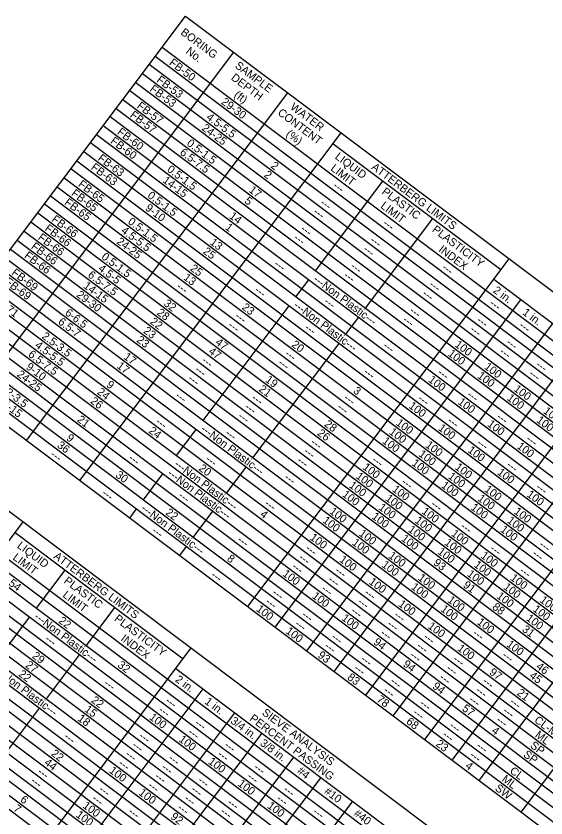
# Model space of a CAD drawing. Extents: x 627484.2 to 627514.4, y 367972.1 to 367996.9.
# Drawn here: x 627508.72 to 627512.36, y 367980.14 to 367985.65 of the extents above; entities that cross this region are included whole.
import ezdxf

# ---------------------------------------------------------------- set-up
doc = ezdxf.new("R2010")
doc.units = 0
doc.layers.add('Default', color=7, linetype='Continuous')
doc.layers.add('R_Survey Control', color=7, linetype='Continuous')

msp = doc.modelspace()

# ---------------------------------------------------------------- linework, layer by layer
at = {"layer": 'Default'}
for p, q in [((627508.0877, 367983.2583), (627509.8821, 367985.648)), ((627509.8821, 367985.648), (627514.3574, 367982.2875)), ((627508.4191, 367983.0095), (627510.2135, 367985.3992)), ((627509.7211, 367985.4336), (627514.1964, 367982.0731)), ((627509.6743, 367985.3712), (627514.1495, 367982.0107)), ((627509.6333, 367985.3166), (627514.1086, 367981.9561)), ((627509.5865, 367985.2543), (627514.0617, 367981.8938)), ((627509.5396, 367985.1919), (627514.0149, 367981.8314)), ((627509.4987, 367985.1373), (627513.9739, 367981.7768)), ((627508.7894, 367982.7314), (627510.5838, 367985.1211)), ((627509.4518, 367985.075), (627513.9271, 367981.7145)), ((627509.405, 367985.0126), (627513.8802, 367981.6521)), ((627509.364, 367984.958), (627513.8393, 367981.5975)), ((627509.1559, 367982.4563), (627510.9503, 367984.8459)), ((627509.3172, 367984.8956), (627513.7924, 367981.5351)), ((627509.2703, 367984.8333), (627513.7456, 367981.4728)), ((627509.2294, 367984.7787), (627513.7046, 367981.4182)), ((627510.8947, 367984.7719), (627512.0486, 367983.9054)), ((627509.1825, 367984.7163), (627513.6578, 367981.3558)), ((627509.1357, 367984.6539), (627513.6109, 367981.2934)), ((627509.0947, 367984.5994), (627513.57, 367981.2389)), ((627509.0479, 367984.537), (627513.5231, 367981.1765)), ((627509.001, 367984.4746), (627513.4763, 367981.1141)), ((627510.7752, 367983.8983), (627511.2377, 367984.5143)), ((627508.9542, 367984.4122), (627513.4294, 367981.0517)), ((627508.9132, 367984.3577), (627513.3885, 367980.9972)), ((627508.8664, 367984.2953), (627513.3416, 367980.9348)), ((627511.1182, 367983.6407), (627511.5808, 367984.2567)), ((627508.8195, 367984.2329), (627513.2948, 367980.8724)), ((627508.7727, 367984.1705), (627513.248, 367980.81)), ((627508.7259, 367984.1082), (627513.2011, 367980.7477)), ((627508.679, 367984.0458), (627513.1543, 367980.6853)), ((627508.638, 367983.9912), (627513.1133, 367980.6307)), ((627510.3098, 367981.5898), (627512.1042, 367983.9795)), ((627508.5912, 367983.9289), (627513.0665, 367980.5684)), ((627508.5444, 367983.8665), (627513.0196, 367980.506)), ((627508.5034, 367983.8119), (627512.9786, 367980.4514)), ((627510.6405, 367983.719), (627510.7284, 367983.836)), ((627511.9988, 367983.8391), (627513.5893, 367982.6448)), ((627508.4566, 367983.7495), (627512.9318, 367980.389)), ((627510.4969, 367981.4493), (627512.1859, 367983.6986)), ((627508.4097, 367983.6872), (627512.885, 367980.3267)), ((627510.0024, 367982.8692), (627510.5937, 367983.6566)), ((627508.3629, 367983.6248), (627512.8381, 367980.2643)), ((627510.9836, 367983.4614), (627511.0714, 367983.5784)), ((627508.3161, 367983.5624), (627512.7913, 367980.2019)), ((627510.7152, 367981.2854), (627512.4042, 367983.5347)), ((627508.2692, 367983.5), (627512.7445, 367980.1395)), ((627508.2282, 367983.4455), (627512.7035, 367980.085)), ((627508.1814, 367983.3831), (627512.6566, 367980.0226)), ((627510.3454, 367982.6116), (627510.9368, 367983.399)), ((627510.9023, 367981.1449), (627512.5913, 367983.3942)), ((627508.1346, 367983.3207), (627512.6098, 367979.9602)), ((627508.0877, 367983.2583), (627512.563, 367979.8978)), ((627511.1206, 367980.9809), (627512.8096, 367983.2303)), ((627511.3077, 367980.8404), (627512.9968, 367983.0897)), ((627507.6986, 367982.9746), (627512.1738, 367979.6141)), ((627511.526, 367980.6765), (627513.2151, 367982.9258)), ((627507.5376, 367982.7602), (627512.0128, 367979.3997)), ((627509.8209, 367982.6275), (627509.9556, 367982.8068)), ((627511.7131, 367980.536), (627513.4022, 367982.7853)), ((627511.9003, 367980.3955), (627513.6947, 367982.7851)), ((627507.4937, 367982.7017), (627511.9689, 367979.3412)), ((627507.4468, 367982.6393), (627511.9221, 367979.2788)), ((627507.4, 367982.5769), (627511.8753, 367979.2164)), ((627510.164, 367982.3699), (627510.2986, 367982.5492)), ((627512.1887, 367980.1789), (627513.9831, 367982.5685)), ((627507.3532, 367982.5146), (627511.8284, 367979.1541)), ((627509.5926, 367982.3234), (627509.7272, 367982.5027)), ((627507.3122, 367982.46), (627511.7874, 367979.0995)), ((627507.2654, 367982.3976), (627511.7406, 367979.0371)), ((627507.2185, 367982.3352), (627511.6938, 367978.9747)), ((627507.1717, 367982.2729), (627511.6469, 367978.9124)), ((627509.4989, 367982.1987), (627509.5457, 367982.261)), ((627507.1248, 367982.2105), (627511.6001, 367978.85)), ((627509.9356, 367982.0658), (627510.0703, 367982.2451)), ((627506.9577, 367979.7633), (627508.7667, 367982.1725)), ((627507.078, 367982.1481), (627511.5533, 367978.7876)), ((627507.037, 367982.0936), (627511.5123, 367978.733)), ((627508.7111, 367982.0984), (627509.865, 367981.232)), ((627506.9902, 367982.0312), (627511.4654, 367978.6707)), ((627509.842, 367981.9411), (627509.8888, 367982.0034)), ((627506.9434, 367981.9688), (627511.4186, 367978.6083)), ((627506.8965, 367981.9064), (627511.3718, 367978.5459)), ((627506.8497, 367981.8441), (627511.3249, 367978.4836)), ((627508.858, 367981.5796), (627509.0542, 367981.8408)), ((627506.8087, 367981.7895), (627511.2839, 367978.429)), ((627506.7619, 367981.7271), (627511.2371, 367978.3666)), ((627506.715, 367981.6647), (627511.1903, 367978.3042)), ((627509.2011, 367981.322), (627509.3972, 367981.5832)), ((627508.5829, 367981.2132), (627508.8112, 367981.5173)), ((627508.1116, 367978.8969), (627509.9206, 367981.306)), ((627508.9259, 367980.9556), (627509.1542, 367981.2597)), ((627509.8152, 367981.1657), (627511.4057, 367979.9714)), ((627508.2987, 367978.7564), (627510.0024, 367981.0252)), ((627508.0126, 367979.7393), (627508.8791, 367980.8932)), ((627508.517, 367978.5924), (627510.2207, 367980.8613)), ((627508.7041, 367978.4519), (627510.4078, 367980.7207)), ((627508.9224, 367978.288), (627510.6261, 367980.5568)), ((627509.1095, 367978.1475), (627510.8132, 367980.4163)), ((627509.3278, 367977.9836), (627511.0315, 367980.2524))]:
    msp.add_line(p, q, dxfattribs=at)
at = {"layer": 'R_Survey Control'}
msp.add_line((627509.8821, 367985.648), (627509.8821, 367985.648), dxfattribs=at)

# ---------------------------------------------------------------- texts
at = {"layer": 'Default'}
for s, p in [('BORING', (627509.844, 367985.5262)), ('No.', (627509.8796, 367985.3963)), ('FB-50', (627509.765, 367985.3175)), ('SAMPLE', (627510.2171, 367985.2976)), ('FB-53', (627509.6787, 367985.1994)), ('DEPTH', (627510.1902, 367985.2146)), ('FB-53', (627509.6319, 367985.137)), ('(ft)', (627510.21, 367985.0966)), ('29-30', (627510.1231, 367985.0486)), ('FB-57', (627509.5428, 367985.021)), ('WATER', (627510.5964, 367985.0128)), ('FB-57', (627509.496, 367984.9586)), ('4.5-5.5', (627510.02, 367984.9431)), ('CONTENT', (627510.5104, 367984.9742)), ('24-25', (627509.9894, 367984.8686)), ('FB-60', (627509.4079, 367984.8419)), ('(%)', (627510.5676, 367984.8281)), ('FB-60', (627509.3611, 367984.7795)), ('0.5-1.5', (627509.8854, 367984.7638)), ('6.5-7.5', (627509.8385, 367984.7014)), ('FB-63', (627509.2748, 367984.6614)), ('LIQUID', (627510.9038, 367984.6724)), ('FB-63', (627509.2279, 367984.599)), ('2', (627510.4634, 367984.6102)), ('LIMIT', (627510.874, 367984.5917)), ('ATTERBERG LIMITS', (627511.1544, 367984.6004)), ('0.5-1.5', (627509.7507, 367984.5845)), ('2', (627510.4166, 367984.5478)), ('FB-65', (627509.1396, 367984.4825)), ('14-15', (627509.7201, 367984.5099)), ('FB-65', (627509.0927, 367984.4201)), ('17', (627510.3126, 367984.443)), ('---', (627510.8897, 367984.473)), ('PLASTIC', (627511.2256, 367984.4308)), ('0.5-1.5', (627509.6161, 367984.4051)), ('5', (627510.2827, 367984.3679)), ('FB-65', (627509.0459, 367984.3578)), ('9-10', (627509.6007, 367984.3191)), ('---', (627510.8019, 367984.356)), ('LIMIT', (627511.217, 367984.3341)), ('14', (627510.1776, 367984.2639)), ('---', (627510.755, 367984.2936)), ('FB-66', (627508.9572, 367984.2415)), ('0.5-1.5', (627509.4814, 367984.2258)), ('FB-66', (627508.9103, 367984.1791)), ('4.5-5.5', (627509.4346, 367984.1635)), ('1', (627510.1499, 367984.1872)), ('---', (627510.6672, 367984.1767)), ('---', (627511.2327, 367984.2154)), ('PLASTICITY', (627511.5718, 367984.1709)), ('FB-66', (627508.8635, 367984.1167)), ('---', (627510.6204, 367984.1143)), ('FB-66', (627508.8167, 367984.0544)), ('24-25', (627509.404, 367984.0889)), ('13', (627510.0446, 367984.0834)), ('---', (627511.1449, 367984.0984)), ('INDEX', (627511.6161, 367984.0344)), ('FB-66', (627508.7698, 367983.992)), ('0.5-1.5', (627509.2999, 367983.9841)), ('25', (627509.9972, 367984.0214)), ('---', (627511.0981, 367984.036)), ('FB-69', (627508.6822, 367983.8749)), ('4.5-5', (627509.2774, 367983.9035)), ('25', (627509.9093, 367983.9045)), ('---', (627510.4857, 367983.935)), ('---', (627511.0103, 367983.9191)), ('---', (627511.6382, 367983.9109)), ('6.5-7.5', (627509.2062, 367983.8594)), ('13', (627509.8631, 367983.8417)), ('---', (627510.9634, 367983.8567)), ('FB-69', (627508.6353, 367983.8126)), ('14-15', (627509.1756, 367983.7848)), ('---Non Plastic---', (627510.7548, 367983.8305)), ('---', (627511.5503, 367983.794)), ('29-30', (627509.1278, 367983.7232)), ('---', (627509.8148, 367983.7804)), ('---', (627510.3511, 367983.7557)), ('---', (627511.5035, 367983.7316)), ('2 in.', (627511.9898, 367983.7536)), ('FB-71', (627508.5501, 367983.6937)), ('32', (627509.7271, 367983.6634)), ('---', (627510.8288, 367983.6774)), ('6-6.5', (627509.0491, 367983.5994)), ('28', (627509.6807, 367983.6006)), ('23', (627510.2646, 367983.6377)), ('---Non Plastic---', (627510.6202, 367983.6511)), ('---', (627511.9656, 367983.665)), ('1 in.', (627512.1925, 367983.6014)), ('---', (627510.2164, 367983.5764)), ('---', (627511.4157, 367983.6147)), ('6.5-7', (627509.0016, 367983.5375)), ('22', (627509.6334, 367983.5386)), ('---', (627510.1696, 367983.514)), ('---', (627511.3689, 367983.5523)), ('---', (627511.8778, 367983.5481)), ('---', (627512.1683, 367983.5128)), ('2.5-3.5', (627508.8901, 367983.4384)), ('23', (627509.5879, 367983.4753)), ('---', (627510.6941, 367983.4981)), ('---', (627511.831, 367983.4857)), ('23', (627509.5411, 367983.4129)), ('47', (627510.0819, 367983.3969)), ('20', (627510.6061, 367983.3812)), ('100', (627511.7267, 367983.3811)), ('---', (627512.0805, 367983.3959)), ('4.5-5.5', (627508.8433, 367983.376)), ('47', (627510.0351, 367983.3346)), ('---', (627511.2342, 367983.373)), ('6.5-7.5', (627508.7964, 367983.3136)), ('17', (627509.452, 367983.2969)), ('---', (627510.5595, 367983.3188)), ('100', (627511.6799, 367983.3187)), ('---', (627512.0337, 367983.3335)), ('9-10', (627508.7811, 367983.2276)), ('17', (627509.4052, 367983.2345)), ('---', (627509.9881, 367983.2723)), ('---', (627510.5126, 367983.2564)), ('100', (627511.9295, 367983.2289)), ('---', (627512.2832, 367983.2437)), ('24-25', (627508.719, 367983.1767)), ('---', (627509.9413, 367983.2099)), ('---', (627511.0995, 367983.1936)), ('---', (627511.6085, 367983.1894)), ('100', (627511.8826, 367983.1665)), ('---', (627512.2364, 367983.1813)), ('9', (627509.3335, 367983.1054)), ('---', (627509.8944, 367983.1475)), ('19', (627510.4249, 367983.1394)), ('100', (627511.5453, 367983.1394)), ('2-3.5', (627508.6393, 367983.0536)), ('24', (627509.2702, 367983.0554)), ('21', (627510.3806, 367983.0751)), ('3', (627511.0294, 367983.0634)), ('100', (627512.1322, 367983.0766)), ('14-15', (627508.5843, 367982.9974)), ('26', (627509.2235, 367982.993)), ('---', (627509.8066, 367983.0306)), ('---', (627510.3311, 367983.0147)), ('---', (627510.9649, 367983.0143)), ('---', (627511.4738, 367983.0101)), ('---', (627511.8112, 367983.0372)), ('100', (627512.0853, 367983.0143)), ('100', (627511.4106, 367982.9601)), ('100', (627511.748, 367982.9872)), ('---', (627510.2843, 367982.9523)), ('---', (627510.9181, 367982.9519)), ('100', (627512.3349, 367982.9244)), ('21', (627509.1325, 367982.8662)), ('---', (627509.6719, 367982.8513)), ('---', (627510.2375, 367982.8899)), ('28', (627510.8308, 367982.8346)), ('100', (627511.3228, 367982.8431)), ('---', (627511.6766, 367982.8579)), ('100', (627511.9507, 367982.835)), ('---', (627512.0139, 367982.885)), ('100', (627512.288, 367982.8621)), ('24', (627509.6249, 367982.789)), ('---Non Plastic---', (627509.982, 367982.8013)), ('26', (627510.7833, 367982.7727)), ('100', (627511.2759, 367982.7807)), ('100', (627511.6133, 367982.8078)), ('9', (627509.0584, 367982.739)), ('---', (627510.1497, 367982.773)), ('36', (627508.9951, 367982.6889)), ('---', (627510.7366, 367982.7102)), ('100', (627511.2291, 367982.7184)), ('100', (627511.5255, 367982.6909)), ('---', (627511.8793, 367982.7057)), ('100', (627512.1534, 367982.6827)), ('---', (627512.2166, 367982.7328)), ('---', (627508.9484, 367982.6265)), ('---', (627510.6897, 367982.6479)), ('100', (627511.4787, 367982.6285)), ('100', (627511.816, 367982.6556)), ('---', (627509.4846, 367982.6018)), ('---', (627510.015, 367982.5937)), ('---', (627510.6429, 367982.5855)), ('---', (627511.1577, 367982.5891)), ('100', (627511.4318, 367982.5662)), ('---Non Plastic---', (627509.8006, 367982.5596)), ('20', (627509.968, 367982.5314)), ('100', (627511.0945, 367982.5391)), ('100', (627511.7282, 367982.5387)), ('100', (627512.0187, 367982.5034)), ('---', (627512.082, 367982.5535)), ('30', (627509.3966, 367982.4849)), ('---Non Plastic---', (627509.7537, 367982.4972)), ('---', (627510.5551, 367982.4686)), ('100', (627511.0476, 367982.4767)), ('100', (627511.6814, 367982.4763)), ('100', (627511.0008, 367982.4143)), ('---', (627511.3604, 367982.4369)), ('100', (627511.6345, 367982.4139)), ('---', (627509.3031, 367982.3601)), ('100', (627510.9539, 367982.3519)), ('100', (627511.2972, 367982.3868)), ('100', (627511.9309, 367982.3865)), ('100', (627512.2214, 367982.3512)), ('---', (627512.2847, 367982.4012)), ('---', (627509.8277, 367982.3442)), ('100', (627511.2503, 367982.3245)), ('100', (627511.8841, 367982.3241)), ('---Non Plastic---', (627509.5722, 367982.2555)), ('22', (627509.7399, 367982.2272)), ('---', (627510.4204, 367982.2892)), ('100', (627510.8661, 367982.235)), ('100', (627511.2035, 367982.2621)), ('100', (627511.4999, 367982.2346)), ('---', (627511.5631, 367982.2847)), ('100', (627511.8372, 367982.2617)), ('100', (627512.1336, 367982.2342)), ('4', (627510.3896, 367982.2148)), ('100', (627510.8193, 367982.1726)), ('100', (627511.1567, 367982.1997)), ('100', (627511.453, 367982.1722)), ('100', (627512.0868, 367982.1719)), ('---', (627511.7658, 367982.1325)), ('---', (627509.6462, 367982.1025)), ('100', (627511.0688, 367982.0828)), ('100', (627511.4062, 367982.1099)), ('100', (627511.7026, 367982.0824)), ('100', (627512.04, 367982.1095)), ('LIQUID', (627508.7203, 367981.999)), ('---', (627510.2331, 367982.0397)), ('100', (627510.7315, 367982.0557)), ('100', (627511.022, 367982.0204)), ('100', (627511.3594, 367982.0475)), ('100', (627511.6558, 367982.02)), ('---', (627510.701, 367981.981)), ('100', (627511.6089, 367981.9577)), ('---', (627511.9685, 367981.9802)), ('---', (627512.3059, 367982.0073)), ('LIMIT', (627508.6904, 367981.9183)), ('ATTERBERG LIMITS', (627508.9708, 367981.9269)), ('8', (627510.162, 367981.9102)), ('---', (627510.6542, 367981.9186)), ('100', (627510.9342, 367981.9034)), ('100', (627511.2715, 367981.9305)), ('100', (627511.9053, 367981.9302)), ('---', (627512.2591, 367981.945)), ('---', (627510.6074, 367981.8562)), ('100', (627511.2247, 367981.8682)), ('93', (627511.5799, 367981.8819)), ('100', (627511.8585, 367981.8678)), ('---', (627510.0516, 367981.798)), ('100', (627510.5441, 367981.8062)), ('---', (627510.9038, 367981.8288)), ('100', (627511.8116, 367981.8054)), ('---', (627512.1713, 367981.828)), ('54', (627508.662, 367981.7412)), ('PLASTIC', (627509.0421, 367981.7574)), ('---', (627510.8569, 367981.7664)), ('100', (627511.1369, 367981.7512)), ('100', (627511.4743, 367981.7783)), ('91', (627511.7839, 367981.7287)), ('100', (627512.108, 367981.778)), ('---', (627510.8101, 367981.704)), ('100', (627511.4274, 367981.716)), ('100', (627512.0612, 367981.7156)), ('LIMIT', (627509.0335, 367981.6607)), ('---', (627510.4727, 367981.6769)), ('100', (627510.7468, 367981.654)), ('---', (627511.1065, 367981.6765)), ('100', (627511.677, 367981.6261)), ('100', (627512.0143, 367981.6532)), ('100', (627512.3107, 367981.6257)), ('100', (627510.3626, 367981.5645)), ('---', (627510.4259, 367981.6145)), ('---', (627511.0596, 367981.6142)), ('100', (627511.3396, 367981.599)), ('100', (627511.6301, 367981.5637)), ('88', (627511.9845, 367981.5781)), ('100', (627512.2639, 367981.5634)), ('---', (627510.6754, 367981.5247)), ('---', (627511.0128, 367981.5518)), ('---', (627511.3092, 367981.5243)), ('---Non Plastic---', (627508.8377, 367981.5118)), ('22', (627509.0053, 367981.4834)), ('PLASTICITY', (627509.3882, 367981.4974)), ('100', (627510.9496, 367981.5017)), ('100', (627511.8797, 367981.4739)), ('100', (627512.2171, 367981.501)), ('100', (627510.5653, 367981.4123)), ('---', (627510.6286, 367981.4623)), ('---', (627511.2623, 367981.4619)), ('100', (627511.5423, 367981.4468)), ('31', (627512.1893, 367981.4243)), ('---', (627508.9116, 367981.3587)), ('INDEX', (627509.4325, 367981.361)), ('---', (627510.8781, 367981.3725)), ('94', (627511.1685, 367981.3373)), ('---', (627511.2155, 367981.3996)), ('---', (627511.5119, 367981.3721)), ('---', (627511.8493, 367981.3992)), ('---', (627510.8313, 367981.3101)), ('---', (627511.4651, 367981.3097)), ('100', (627511.745, 367981.2946)), ('100', (627512.0824, 367981.3217)), ('29', (627508.8239, 367981.2417)), ('93', (627510.7859, 367981.2467)), ('---', (627511.4182, 367981.2474)), ('---', (627512.052, 367981.247)), ('27', (627508.7771, 367981.1793)), ('32', (627509.4107, 367981.179)), ('---', (627511.0808, 367981.2202)), ('94', (627511.3712, 367981.1851)), ('---', (627511.7146, 367981.2199)), ('---Non Plastic---', (627508.5625, 367981.1453)), ('---', (627511.034, 367981.1579)), ('---', (627511.6678, 367981.1575)), ('97', (627511.9643, 367981.1299)), ('46', (627512.2858, 367981.1689)), ('22', (627508.7302, 367981.117)), ('2 in.', (627509.8062, 367981.0801)), ('83', (627510.9886, 367981.0945)), ('---', (627511.6209, 367981.0951)), ('45', (627512.2399, 367981.1059)), ('---', (627509.317, 367981.0543)), ('---', (627511.2836, 367981.068)), ('94', (627511.5739, 367981.0329)), ('---', (627511.9173, 367981.0677)), ('---', (627511.2367, 367981.0057)), ('---', (627511.8705, 367981.0053)), ('21', (627512.1539, 367980.9875)), ('22', (627509.2292, 367980.9373)), ('---', (627509.7382, 367980.9331)), ('1 in.', (627510.0089, 367980.9279)), ('78', (627511.1904, 367980.9429)), ('---', (627511.8236, 367980.9429)), ('---', (627512.1044, 367980.9272)), ('15', (627509.1832, 367980.8743)), ('---', (627509.6913, 367980.8708)), ('SIEVE ANALYSIS', (627510.4025, 367980.8516)), ('---', (627511.4863, 367980.9158)), ('57', (627511.7769, 367980.8804)), ('---', (627512.0576, 367980.8648)), ('18', (627509.1361, 367980.8122)), ('100', (627509.6281, 367980.8207)), ('3/4 in.', (627510.1863, 367980.7947)), ('PERCENT PASSING', (627510.3177, 367980.8121)), ('68', (627511.3931, 367980.7907)), ('---', (627511.4394, 367980.8534)), ('CL-ML', (627512.2731, 367980.8005)), ('---', (627509.9409, 367980.7809)), ('---', (627511.689, 367980.7636)), ('---', (627512.0108, 367980.8024)), ('---', (627509.894, 367980.7185)), ('---', (627511.6421, 367980.7012)), ('4', (627511.98, 367980.728)), ('ML', (627512.2785, 367980.6989)), ('---', (627509.0419, 367980.6878)), ('---', (627509.5567, 367980.6914)), ('100', (627509.8308, 367980.6685)), ('3/8 in.', (627510.389, 367980.6425)), ('23', (627511.5967, 367980.6378)), ('SP', (627512.2448, 367980.6267)), ('22', (627508.9541, 367980.5709)), ('---', (627509.5098, 367980.6291)), ('---', (627510.1436, 367980.6287)), ('---', (627511.8761, 367980.6231)), ('---', (627509.463, 367980.5667)), ('---', (627509.7594, 367980.5392)), ('100', (627510.0335, 367980.5163)), ('---', (627510.0967, 367980.5663)), ('---', (627511.8293, 367980.5607)), ('SP', (627512.1979, 367980.5643)), ('44', (627508.907, 367980.5087)), ('---', (627509.4162, 367980.5043)), ('---', (627509.7125, 367980.4768)), ('---', (627510.3463, 367980.4765)), ('4', (627511.7985, 367980.4863)), ('---', (627508.8604, 367980.4461)), ('100', (627509.3529, 367980.4543)), ('#4', (627510.6441, 367980.451)), ('CL', (627512.1043, 367980.4518)), ('---', (627508.8135, 367980.3838)), ('---', (627509.6657, 367980.4145)), ('---', (627509.9621, 367980.387)), ('100', (627510.2362, 367980.364)), ('---', (627510.2995, 367980.4141)), ('ML', (627512.0502, 367980.3948)), ('---', (627509.2815, 367980.325)), ('100', (627509.5556, 367980.302)), ('---', (627509.6189, 367980.3521)), ('---', (627509.9153, 367980.3246)), ('---', (627510.549, 367980.3243)), ('#10', (627510.8304, 367980.3111)), ('SW', (627512.0029, 367980.3328)), ('6', (627508.7419, 367980.2547)), ('---', (627509.2347, 367980.2626)), ('---', (627509.8684, 367980.2622)), ('---', (627510.5022, 367980.2619)), ('7', (627508.6953, 367980.1921)), ('100', (627509.1714, 367980.2126)), ('---', (627509.8216, 367980.1999)), ('---', (627510.1648, 367980.2348)), ('100', (627510.4389, 367980.2118)), ('100', (627509.1246, 367980.1502)), ('---', (627509.4842, 367980.1728)), ('92', (627509.7748, 367980.1375)), ('---', (627510.118, 367980.1724)), ('---', (627510.7517, 367980.172)), ('#40', (627511.0331, 367980.1589))]:
    msp.add_text(s, height=0.055, rotation=323.0968, dxfattribs=at).set_placement(p)

doc.saveas('drawing.dxf')
